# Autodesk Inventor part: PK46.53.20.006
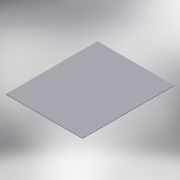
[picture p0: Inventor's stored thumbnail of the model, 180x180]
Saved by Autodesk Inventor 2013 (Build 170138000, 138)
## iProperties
Created: 2005-06
Part Number: PK46.53.20.006
Material: Steel, Mild
Document SubType Name: Modeling
Designer: HKostja
Manufacturer: Standard
Standards Organization: Custom
Density: 7.86 g/cm^3
Mass: 4737.22 g
Surface Area: 4072 cm^2
Volume: 602.7 cm^3
Author: HKostja
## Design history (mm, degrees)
sketch "Эскиз1"
  geometry: L1 (0, 0)-(-410, 0); L2 (-410, 0)-(-410, 490); L3 (-410, 490)-(0, 490); L4 (0, 490)-(0, 0)
  constraints: 8 end point, 2 parallel, 1 horizontal, 1 perpendicular, 1 other
  dimensions: "d0" = 410 distance of L1.start L1.end; "d1" = 490 distance of L3.end L1.start
extrude "Выдавливание1" new body sketch "Эскиз1" distance "d2" = 3; taper "d3" = 0 deg
body "Solid1"
